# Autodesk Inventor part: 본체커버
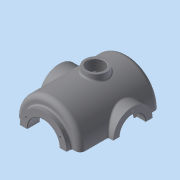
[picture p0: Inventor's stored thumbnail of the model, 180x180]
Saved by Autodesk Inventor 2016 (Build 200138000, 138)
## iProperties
Created: 2016-02
Part Number: 본체커버
Material: 알루미늄 6061
Document SubType Name: Modeling
Designer: mduedu
Density: 2.71 g/cm^3
Appearance: 기본값
Mass: 1187.07 g
Surface Area: 904.884 cm^2
Volume: 438.034 cm^3
Author: mduedu
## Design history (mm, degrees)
sketch "스케치2"
  geometry: L1 (0, 90)-(0, -90); L2 (65, -65.993)-(65, 90); L3 (65, 90)-(0, 90); A1 r 100 centre (0, 10) between (0, -90) and (65, -65.993); 2 further points
  constraints: 6 end point, 2 point on circle, 1 centre point, 1 coincident, 1 horizontal, 1 midpoint, 1 parallel, 1 point on line, 1 vertical
  dimensions: "d3" = 180 distance of L1.start L1.end; "d5" = 130 diameter of L2 L1; "d6" = 100 radius of A1
revolve "회전1" sketch "스케치2" stored, may be unused: angle "d7" = 90 deg
sketch "스케치3"
  geometry: C1 r 47.5 at (0, 0); 1 further point
  constraints: 1 centre point, 1 coincident
  dimensions: "d8" = 95 diameter of C1
extrude "돌출2" join sketch "스케치3" distance "d10" = 10; taper "d11" = 0 deg
sketch "스케치5"
  geometry: L1 (47.5, 100)-(47.5, 90) reference; L2 (47.5, 90)-(65, 90) reference; L3 (65, 90)-(65, -65.993) reference; L4 (-65, -65.993)-(-65, 90) reference; L5 (-65, 90)-(-47.5, 90) reference; L6 (-47.5, 90)-(-47.5, 100) reference; L7 (-47.5, 100)-(47.5, 100) reference; L8 (55, 75)-(55, -61.239); L9 (0, 75)-(55, 75); L10 (0, 75)-(0, -80); A1 r 100 centre (0, 10) between (-65, -65.993) and (0, -90) reference; A2 r 100 centre (0, 10) between (0, -90) and (65, -65.993) reference; A3 r 90 centre (0, 10) between (0, -80) and (55, -61.239); 1 further point
  constraints: 6 end point, 2 point on circle, 1 centre point, 1 parallel, 1 perpendicular, 1 point on line, 1 vertical
  dimensions: "d13" = 10 distance between parallel lines of L3 L8; "d14" = 10 radial gap between concentric circles of A3 A1; "d15" = 15 distance between parallel lines of L9 L2
revolve "회전2" sketch "스케치5" stored, may be unused: angle "d16" = 90 deg
hole "구멍1" diameter "d19" = 65; stored, may be unused: countersink angle "d23" = 90 deg, drill point angle "d25" = 118 deg; dims "d17" = 10, "d18" = 10, "d20" = 6, "d21" = 4, "d22" = 2, "d24" = 8
node "작업 평면1"
sketch "스케치6"
  geometry: L1 (47.5, 100)-(-47.5, 100) reference; C1 r 40 at (0, -7); 1 further point
  constraints: 1 centre point, 1 vertical alignment
  dimensions: "d27" = 80 diameter of C1; "d29" = 107 distance from line of C1.centre L1
extrude "돌출3" join sketch "스케치6" stored distance "d30" = 10; taper "d31" = 0 deg
hole "구멍2" diameter "d34" = 42; stored, may be unused: countersink angle "d38" = 90 deg, drill point angle "d40" = 118 deg; dims "d32" = 10, "d33" = 10, "d35" = 6, "d36" = 52, "d37" = 18, "d39" = 8
sketch "스케치7" dims "d41" = 65
  geometry: C1 r 40 at (0, 0) reference; 3 further points
  constraints: 2 vertical alignment, 1 coincident, 2 other
hole "구멍3" sketch "스케치7" at (0, 32.5) diameter "d43" = 3.242; stored, may be unused: countersink angle "d47" = 90 deg, drill point angle "d49" = 118 deg; dims "d44" = 11, "d45" = 13, "d46" = 18, "d48" = 13
sketch "스케치8" dims "d53" = 80
  geometry: 3 further points
  constraints: 2 vertical alignment, 1 coincident, 2 other
hole "구멍4" sketch "스케치8" at (0, -40) diameter "d56" = 3.242; stored, may be unused: countersink angle "d60" = 90 deg, drill point angle "d62" = 118 deg; dims "d57" = 11, "d58" = 13, "d59" = 18, "d61" = 13
fillet "모깎기1" dims "d66" = 10
fillet "모깎기2" dims "d67" = 3
fillet "모깎기3" dims "d68" = 0.3
chamfer "모따기1" distance "d69" = 1; stored, may be unused: second distance "d70" = 2, angle "d71" = 45 deg
node "작업 평면5"
sketch "스케치10"
  geometry: L1 (-50, 66)-(50, 66); L2 (50, 66)-(50, 50); L3 (50, 50)-(-50, 50); L4 (-50, 50)-(-50, 66); 2 further points
  constraints: 8 end point, 2 horizontal, 2 vertical, 1 midpoint, 1 vertical alignment
  dimensions: "d177" = 50 distance from line of L3 point (0, 0); "d178" = 100 distance of L1.start L1.end; "d179" = 16 distance of L3.end L1.start
extrude "돌출5" join sketch "스케치10" stored distance "d84" = 10; taper "d85" = 0 deg
sketch "스케치21" dims "d180" = 220, "d182" = 130
  geometry: L1 (65, 58)-(-65, 58); L2 (-65, 58)-(-65, -32); L3 (-65, -32)-(65, -32); L4 (65, -32)-(65, 58); L5 (50, 50)-(50, 66) reference; 4 further points
  constraints: 8 end point, 3 horizontal alignment, 3 midpoint, 2 parallel, 1 horizontal, 1 perpendicular, 1 vertical alignment, 4 other
extrude "돌출13" join sketch "스케치21" distance "d183" = 10; taper "d184" = 0 deg
sketch "스케치11"
  geometry: L1 (-65, 80)-(-65, -61.239) reference; L2 (-100, -97)-(-100, -32) reference; L3 (-65, -42.793)-(-100, -63); L4 (-100, -97)-(-110, -97) reference; 1 further point
  constraints: 2 end point, 2 point on line
  dimensions: "d185" = 34 distance from line of L3.end L4; "d186" = 120 deg angle of L2 L3
feature "리브1" sketch "스케치11" dims "d88" = 1, "d89" = 16, "d90" = 0, "d91" = 0, "d92" = 1, "d93" = 1
fillet "모깎기12"
fillet "모깎기13"
fillet "모깎기16" dims "d167" = 3
fillet "모깎기18"
fillet "모깎기17" dims "d168" = 3
fillet "모깎기19" dims "d187" = 3
node "작업 평면6"
sketch "스케치19"
  geometry: L1 (75, -47)-(75, 33) reference; L2 (-75, -47)-(-75, 33) reference; L3 (75, -7)-(-75, -7); C1 r 22.5 at (0, -7); 1 further point
  constraints: 3 midpoint, 2 end point, 1 centre point
  dimensions: "d149" = 45 diameter of C1
extrude "돌출11" join sketch "스케치19" stored distance "d150" = 10; taper "d151" = 0 deg
hole "구멍6" diameter "d154" = 33.376; stored, may be unused: countersink angle "d158" = 90 deg, drill point angle "d160" = 118 deg; dims "d155" = 6, "d156" = 4, "d157" = 2, "d159" = 8, "d190" = 10, "d191" = 10
fillet "모깎기11" dims "d161" = 3
chamfer "모따기3" distance "d164" = 1; stored, may be unused: second distance "d165" = 2, angle "d166" = 45 deg
sketch "스케치22" dims "d189" = 20
  geometry: L1 (-10, -123)-(10, -123); L2 (10, -123)-(10, -103); L3 (10, -103)-(-10, -103); L4 (-10, -103)-(-10, -123); A1 r 65 centre (0, -58) between (-65, -58) and (65, -58) reference; 2 further points
  constraints: 8 end point, 2 parallel, 1 horizontal, 1 horizontal alignment, 1 midpoint, 1 perpendicular, 1 tangent, 1 vertical alignment, 2 other
  dimensions: "d193" = 30 dimension on L1
extrude "돌출14" cut sketch "스케치22" stored distance "d194" = 10; taper "d195" = 0 deg
fillet "모깎기21" dims "d196" = 3
feature "분할1"
node "솔리드2"
pattern_circular "원형 패턴1" dims angle "d51" = 360 deg
mirror "대칭1"
pattern_circular "원형 패턴2" dims angle "d64" = 360 deg
node "절단 모서리 투영1"
other parameters: "d26" = 75, "d136" = 175
